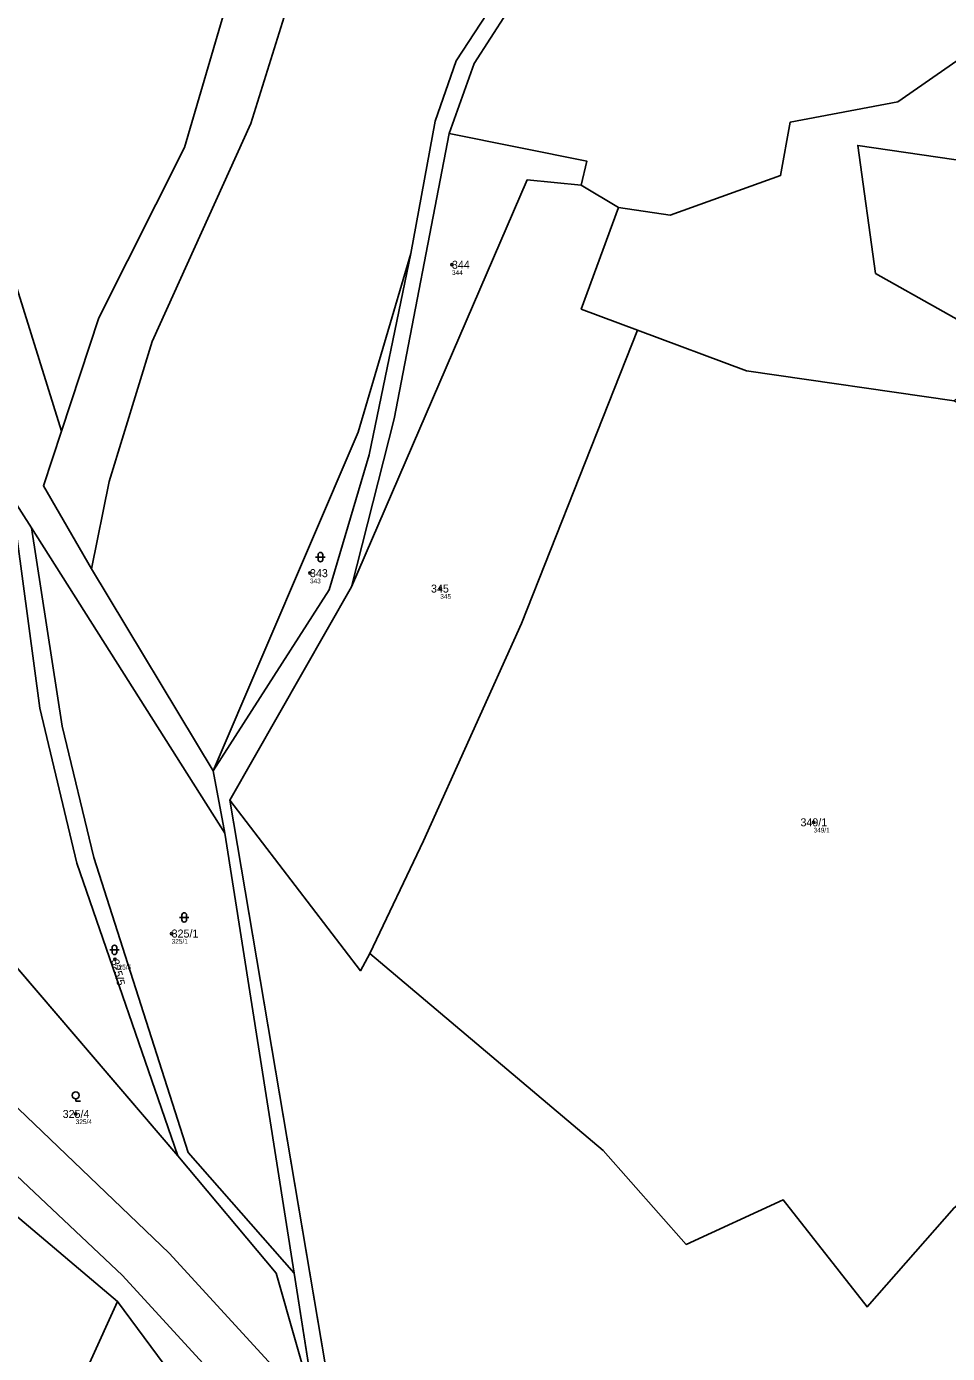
# Model space of a CAD drawing. Extents: x -767985 to -763816, y -1059600 to -1057360.
# Drawn here: x -765968.6 to -765772.9, y -1058497.3 to -1058215.3 of the extents above; entities that cross this region are included whole.
import ezdxf

# ---------------------------------------------------------------- set-up
doc = ezdxf.new("R2010")
doc.units = 0
for name, color, linetype in [('Definiční body', 7, 'Continuous'), ('Hranice parcel', 7, 'Continuous'), ('Parcelní čísla', 7, 'Continuous'), ('Polygon parcely', 7, 'Continuous'), ('Značky kultur', 7, 'Continuous')]:
    doc.layers.add(name, color=color, linetype=linetype)

msp = doc.modelspace()

# ---------------------------------------------------------------- linework, layer by layer
at = {"layer": 'Definiční body'}
for centre in [(-765878.2, -1058265.95994), (-765908.37, -1058331.47994), (-765880.68, -1058334.75994), (-765801.36, -1058384.41994), (-765937.77, -1058408.04994), (-765949.82, -1058413.53994), (-765958.15, -1058446.37994)]:
    msp.add_circle(centre, 0.25, dxfattribs=at)
at = {"layer": 'Hranice parcel'}
for p, q in [((-765850.72, -1058249.07), (-765842.81, -1058253.81)), ((-765967.58, -1058321.82), (-765971.77, -1058315.2)), ((-765926.48, -1058386.74), (-765967.58, -1058321.82)), ((-765928.93, -1058373.47), (-765954.8, -1058330.58)), ((-765925.43, -1058379.74), (-765899.55, -1058334.41)), ((-765926.48, -1058386.74), (-765928.93, -1058373.47)), ((-765902.49, -1058514.97), (-765925.43, -1058379.74)), ((-765911.75, -1058480.2), (-765926.48, -1058386.74)), ((-765936.48, -1058455.29), (-765988.63, -1058394.32)), ((-765949.24, -1058486.24), (-765970.97, -1058467.85)), ((-765907.06, -1058509.99), (-765911.75, -1058480.2))]:
    msp.add_line(p, q, dxfattribs=at)
for points in [[(-765788.09, -1058014.28), (-765802.57, -1058077.06), (-765812.78, -1058103.02), (-765830.89, -1058137.5), (-765856.13, -1058196.23), (-765873.46, -1058223.22), (-765878.76, -1058238.1)], [(-765793.77, -1058023.67), (-765805.15, -1058073.93), (-765815.85, -1058103.33), (-765833.97, -1058134.93), (-765859.02, -1058194.68), (-765877.32, -1058222.64), (-765881.76, -1058235.42), (-765886.96, -1058263.55)], [(-765954.8, -1058330.58), (-765951.07, -1058312.04), (-765941.91, -1058282.28), (-765920.97, -1058235.94), (-765913.14, -1058211.01), (-765896.32, -1058166.83), (-765882.94, -1058129.1), (-765871.49, -1058094.17), (-765862.79, -1058059.14), (-765857.56, -1058027.97)], [(-765876.43, -1058058.91), (-765881.35, -1058082.33), (-765899.83, -1058140.73), (-765915.4, -1058188.6), (-765926.19, -1058210.84), (-765935.05, -1058241.06), (-765953.25, -1058277.24), (-765961.17, -1058301.29)], [(-765961.17, -1058301.29), (-765978.87, -1058244.75), (-765995.2, -1058212.34)], [(-765842.81, -1058253.81), (-765831.83, -1058255.4), (-765808.35, -1058247.02), (-765806.35, -1058235.67), (-765783.41, -1058231.37), (-765770.89, -1058222.6), (-765747.89, -1058223.85), (-765736.9, -1058218.35), (-765722.84, -1058242.26), (-765718.45, -1058234.57)], [(-765878.76, -1058238.1), (-765890.51, -1058298.69), (-765899.55, -1058334.41)], [(-765850.72, -1058249.07), (-765849.52, -1058243.96), (-765878.76, -1058238.1)], [(-765691.07, -1058296.45), (-765714.71, -1058251.91), (-765791.95, -1058240.6), (-765788.22, -1058267.79), (-765759.42, -1058283.94), (-765771.49, -1058294.89)], [(-765899.55, -1058334.41), (-765862.23, -1058247.92), (-765850.72, -1058249.07)], [(-765838.8, -1058279.85), (-765850.73, -1058275.38), (-765842.81, -1058253.81)], [(-765886.96, -1058263.55), (-765898.14, -1058301.53), (-765928.93, -1058373.47)], [(-765928.93, -1058373.47), (-765904.28, -1058335.05), (-765895.8, -1058306.32), (-765886.96, -1058263.55)], [(-765838.8, -1058279.85), (-765863.41, -1058342.21), (-765884.25, -1058388.38), (-765895.65, -1058412.27)], [(-765771.49, -1058294.89), (-765815.61, -1058288.53), (-765838.8, -1058279.85)], [(-765961.17, -1058301.29), (-765965, -1058312.91), (-765954.8, -1058330.58)], [(-765971.77, -1058315.2), (-765965.74, -1058360.18), (-765957.89, -1058393.07), (-765936.48, -1058455.29)], [(-765967.58, -1058321.82), (-765961.05, -1058364.02), (-765954.3, -1058391.92), (-765934.26, -1058454.57), (-765911.75, -1058480.2)], [(-766092.25, -1058373.31), (-766068.95, -1058381.52), (-766041.29, -1058399.4), (-766009.49, -1058422.96), (-765948.22, -1058480.72), (-765893.77, -1058540.14)], [(-765895.65, -1058412.27), (-765897.66, -1058415.96), (-765925.43, -1058379.74)], [(-765895.65, -1058412.27), (-765846.09, -1058454.17), (-765828.43, -1058474.1), (-765807.83, -1058464.6), (-765789.97, -1058487.39), (-765771.5, -1058466.3), (-765755.11, -1058453.62)], [(-765995.67, -1058421.04), (-765938.28, -1058475.97), (-765907.06, -1058509.99)], [(-765907.06, -1058509.99), (-765915.57, -1058480.19), (-765936.48, -1058455.29)], [(-765949.24, -1058486.24), (-765967.46, -1058526.34), (-765975.64, -1058550.3), (-766022.63, -1058667.68), (-766042.69, -1058716.31)], [(-765915.25, -1058521.03), (-765939.32, -1058499.61), (-765949.24, -1058486.24)]]:
    msp.add_lwpolyline(points, dxfattribs=at)
at = {"layer": 'Polygon parcely'}
for points in [[(-765727.95, -1057983.75), (-765788.09, -1058014.28), (-765802.57, -1058077.06), (-765812.78, -1058103.02), (-765830.89, -1058137.5), (-765856.13, -1058196.23), (-765873.46, -1058223.22), (-765878.76, -1058238.1), (-765849.52, -1058243.96), (-765850.72, -1058249.07), (-765842.81, -1058253.81), (-765831.83, -1058255.4), (-765808.35, -1058247.02), (-765806.35, -1058235.67), (-765783.41, -1058231.37), (-765770.89, -1058222.6)], [(-765902.49, -1058514.97), (-765925.43, -1058379.74), (-765899.55, -1058334.41), (-765890.51, -1058298.69), (-765878.76, -1058238.1), (-765873.46, -1058223.22), (-765856.13, -1058196.23), (-765830.89, -1058137.5), (-765812.78, -1058103.02), (-765802.57, -1058077.06), (-765788.09, -1058014.28)], [(-765793.77, -1058023.67), (-765805.15, -1058073.93), (-765815.85, -1058103.33), (-765833.97, -1058134.93), (-765859.02, -1058194.68), (-765877.32, -1058222.64), (-765881.76, -1058235.42), (-765886.96, -1058263.55), (-765895.8, -1058306.32), (-765904.28, -1058335.05), (-765928.93, -1058373.47), (-765926.48, -1058386.74), (-765911.75, -1058480.2), (-765907.06, -1058509.99)], [(-766139.56, -1058061.14), (-766134.75, -1058069.91), (-766085.7, -1058155.04), (-766061.29, -1058172.55), (-766047.12, -1058183.23), (-766023.45, -1058201.07), (-765997.93, -1058227.82), (-765984.33, -1058253.84), (-765974.41, -1058287.25), (-765971.77, -1058315.2), (-765967.58, -1058321.82), (-765926.48, -1058386.74), (-765928.93, -1058373.47), (-765954.8, -1058330.58), (-765965, -1058312.91), (-765961.17, -1058301.29), (-765978.87, -1058244.75), (-765995.2, -1058212.34), (-766007.59, -1058201.19), (-766083.69, -1058146.62), (-766127.9, -1058069.32)], [(-765907.06, -1058509.99), (-765938.28, -1058475.97), (-765995.67, -1058421.04), (-766028.01, -1058394.94), (-766048.15, -1058381.06), (-766060.34, -1058375.22), (-766066.84, -1058372.11), (-766093.28, -1058363.36), (-766109.12, -1058354.36), (-766121.31, -1058346.01), (-766122.51, -1058345.18), (-766127.47, -1058337.9), (-766131.83, -1058328.16), (-766137.71, -1058315.03), (-766144.44, -1058293.9), (-766154.16, -1058263.63), (-766162.06, -1058241.04), (-766179.98, -1058204.86), (-766190.76, -1058186.25)], [(-766183.4, -1058221.59), (-766169.87, -1058250.23), (-766159.52, -1058278.21), (-766150.99, -1058310.19), (-766144.69, -1058328.75), (-766135.72, -1058344.67), (-766124.85, -1058355.68), (-766124.77, -1058361.86), (-766092.25, -1058373.31), (-766068.95, -1058381.52), (-766041.29, -1058399.4), (-766009.49, -1058422.96), (-765948.22, -1058480.72), (-765893.77, -1058540.14)], [(-765770.89, -1058222.6), (-765783.41, -1058231.37), (-765806.35, -1058235.67), (-765808.35, -1058247.02), (-765831.83, -1058255.4), (-765842.81, -1058253.81), (-765850.73, -1058275.38), (-765838.8, -1058279.85), (-765815.61, -1058288.53), (-765771.49, -1058294.89)], [(-765759.42, -1058283.94), (-765788.22, -1058267.79), (-765791.95, -1058240.6), (-765714.71, -1058251.91)], [(-765771.5, -1058466.3), (-765789.97, -1058487.39), (-765807.83, -1058464.6), (-765828.43, -1058474.1), (-765846.09, -1058454.17), (-765895.65, -1058412.27), (-765897.66, -1058415.96), (-765925.43, -1058379.74), (-765902.49, -1058514.97), (-765897.47, -1058520.44), (-765864.89, -1058547.27), (-765835.08, -1058560.96), (-765790.13, -1058560.29), (-765734.53, -1058555.37)]]:
    msp.add_lwpolyline(points, dxfattribs=at)
for points in [[(-765857.56, -1058027.97), (-765862.79, -1058059.14), (-765871.49, -1058094.17), (-765882.94, -1058129.1), (-765896.32, -1058166.83), (-765913.14, -1058211.01), (-765920.97, -1058235.94), (-765941.91, -1058282.28), (-765951.07, -1058312.04), (-765954.8, -1058330.58), (-765928.93, -1058373.47), (-765898.14, -1058301.53), (-765886.96, -1058263.55), (-765881.76, -1058235.42), (-765877.32, -1058222.64), (-765859.02, -1058194.68), (-765833.97, -1058134.93), (-765815.85, -1058103.33), (-765805.15, -1058073.93), (-765793.77, -1058023.67), (-765805.21, -1058024.67), (-765815.5, -1058027.82), (-765838.69, -1058029.38)], [(-765876.43, -1058058.91), (-765881.35, -1058082.33), (-765899.83, -1058140.73), (-765915.4, -1058188.6), (-765926.19, -1058210.84), (-765935.05, -1058241.06), (-765953.25, -1058277.24), (-765961.17, -1058301.29), (-765965, -1058312.91), (-765954.8, -1058330.58), (-765951.07, -1058312.04), (-765941.91, -1058282.28), (-765920.97, -1058235.94), (-765913.14, -1058211.01), (-765896.32, -1058166.83), (-765882.94, -1058129.1), (-765871.49, -1058094.17), (-765862.79, -1058059.14), (-765857.56, -1058027.97), (-765873.82, -1058026.32), (-765873.69, -1058034.34)], [(-765951.27, -1058110.93), (-765967.67, -1058152.53), (-765995.2, -1058212.34), (-765978.87, -1058244.75), (-765961.17, -1058301.29), (-765953.25, -1058277.24), (-765935.05, -1058241.06), (-765926.19, -1058210.84), (-765915.4, -1058188.6), (-765899.83, -1058140.73), (-765881.35, -1058082.33), (-765876.43, -1058058.91), (-765944.68, -1058083.49)], [(-765890.51, -1058298.69), (-765899.55, -1058334.41), (-765862.23, -1058247.92), (-765850.72, -1058249.07), (-765849.52, -1058243.96), (-765878.76, -1058238.1)], [(-765691.07, -1058296.45), (-765714.71, -1058251.91), (-765791.95, -1058240.6), (-765788.22, -1058267.79), (-765759.42, -1058283.94), (-765771.49, -1058294.89), (-765756.55, -1058302.18), (-765750.07, -1058293.12), (-765740.43, -1058290.43), (-765720.71, -1058294.47), (-765711.02, -1058290.59), (-765700.4, -1058295.12), (-765694.57, -1058303.57)], [(-765850.73, -1058275.38), (-765842.81, -1058253.81), (-765850.72, -1058249.07), (-765862.23, -1058247.92), (-765899.55, -1058334.41), (-765925.43, -1058379.74), (-765897.66, -1058415.96), (-765895.65, -1058412.27), (-765884.25, -1058388.38), (-765863.41, -1058342.21), (-765838.8, -1058279.85)], [(-765928.93, -1058373.47), (-765904.28, -1058335.05), (-765895.8, -1058306.32), (-765886.96, -1058263.55), (-765898.14, -1058301.53)], [(-765815.61, -1058288.53), (-765838.8, -1058279.85), (-765863.41, -1058342.21), (-765884.25, -1058388.38), (-765895.65, -1058412.27), (-765846.09, -1058454.17), (-765828.43, -1058474.1), (-765807.83, -1058464.6), (-765789.97, -1058487.39), (-765771.5, -1058466.3), (-765755.11, -1058453.62), (-765719.38, -1058365.61), (-765709.71, -1058328.24), (-765734.79, -1058317.48), (-765756.55, -1058302.18), (-765771.49, -1058294.89)], [(-765988.34, -1058343.38), (-765986.13, -1058369.89), (-765988.63, -1058394.32), (-765936.48, -1058455.29), (-765957.89, -1058393.07), (-765965.74, -1058360.18), (-765971.77, -1058315.2)], [(-765907.06, -1058509.99), (-765911.75, -1058480.2), (-765934.26, -1058454.57), (-765954.3, -1058391.92), (-765961.05, -1058364.02), (-765967.58, -1058321.82), (-765971.77, -1058315.2), (-765965.74, -1058360.18), (-765957.89, -1058393.07), (-765936.48, -1058455.29), (-765915.57, -1058480.19)], [(-765967.58, -1058321.82), (-765961.05, -1058364.02), (-765954.3, -1058391.92), (-765934.26, -1058454.57), (-765911.75, -1058480.2), (-765926.48, -1058386.74)], [(-766095.42, -1058382.27), (-766067.85, -1058388.57), (-766049.88, -1058400.36), (-766034.52, -1058412.06), (-766016.38, -1058429.41), (-765987.29, -1058454.03), (-765970.97, -1058467.85), (-765949.24, -1058486.24), (-765939.32, -1058499.61), (-765915.25, -1058521.03), (-765893.77, -1058540.14), (-765948.22, -1058480.72), (-766009.49, -1058422.96), (-766041.29, -1058399.4), (-766068.95, -1058381.52), (-766092.25, -1058373.31)], [(-765938.28, -1058475.97), (-765907.06, -1058509.99), (-765915.57, -1058480.19), (-765936.48, -1058455.29), (-765988.63, -1058394.32), (-765995.67, -1058421.04)], [(-765970.97, -1058467.85), (-765992.67, -1058517.5), (-766028.19, -1058606.49), (-766031.26, -1058616.02), (-766049.02, -1058660.43), (-766066.43, -1058709.63), (-766042.69, -1058716.31), (-766022.63, -1058667.68), (-765975.64, -1058550.3), (-765967.46, -1058526.34), (-765949.24, -1058486.24)], [(-765967.46, -1058526.34), (-765975.64, -1058550.3), (-766022.63, -1058667.68), (-766042.69, -1058716.31), (-766024.85, -1058725.9), (-765997.26, -1058748.82), (-765970.63, -1058682.65), (-765969.81, -1058676.38), (-765955.46, -1058639.14), (-765946.75, -1058613.53), (-765930.78, -1058556.44), (-765915.25, -1058521.03), (-765939.32, -1058499.61), (-765949.24, -1058486.24)]]:
    msp.add_lwpolyline(points, close=True, dxfattribs=at)
at = {"layer": 'Značky kultur'}
for p, q in [((-765907.161, -1058328.071), (-765905.159, -1058328.071)), ((-765906.661, -1058327.571), (-765906.661, -1058328.572)), ((-765905.659, -1058328.572), (-765905.659, -1058327.571)), ((-765936.091, -1058404.631), (-765934.089, -1058404.631)), ((-765935.591, -1058404.131), (-765935.591, -1058405.132)), ((-765934.589, -1058405.132), (-765934.589, -1058404.131)), ((-765950.421, -1058411.021), (-765950.421, -1058412.022)), ((-765949.419, -1058412.022), (-765949.419, -1058411.021)), ((-765950.921, -1058411.521), (-765948.919, -1058411.521)), ((-765958.15, -1058443.182), (-765958.15, -1058443.68)), ((-765958.15, -1058443.68), (-765957.149, -1058443.68))]:
    msp.add_line(p, q, dxfattribs=at)
msp.add_circle((-765958.14929, -1058442.4309), 0.75, dxfattribs=at)
for centre, start, end in [((-765906.16, -1058327.5709), 0, 180), ((-765906.16, -1058328.5709), 180, 359.9878861), ((-765935.09, -1058404.1309), 0, 180), ((-765935.09, -1058405.1309), 180, 359.9878861), ((-765949.92, -1058411.0209), 0, 180), ((-765949.92, -1058412.0209), 180, 359.9878861)]:
    msp.add_arc(centre, 0.5, start, end, dxfattribs=at)

# ---------------------------------------------------------------- texts
at = {"layer": 'Definiční body'}
for s, p in [('344', (-765878.2, -1058268.116)), ('343', (-765908.37, -1058333.636)), ('345', (-765880.68, -1058336.916)), ('349/1', (-765801.36, -1058386.576)), ('325/1', (-765937.77, -1058410.206)), ('325/5', (-765949.82, -1058415.696)), ('325/4', (-765958.15, -1058448.536))]:
    msp.add_text(s, height=0.999996, dxfattribs=at).set_placement(p)
at = {"layer": 'Parcelní čísla'}
for s, p in [('344', (-765878.2, -1058266.81)), ('343', (-765908.37, -1058332.33)), ('345', (-765882.654, -1058335.61)), ('349/1', (-765804.133, -1058385.27)), ('325/1', (-765937.77, -1058408.9)), ('325/4', (-765960.923, -1058447.23))]:
    msp.add_text(s, height=1.699998, dxfattribs=at).set_placement(p)
msp.add_text('325/5', height=1.699998, rotation=284, dxfattribs=at).set_placement((-765950.644, -1058413.745))

doc.saveas('drawing.dxf')
